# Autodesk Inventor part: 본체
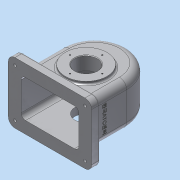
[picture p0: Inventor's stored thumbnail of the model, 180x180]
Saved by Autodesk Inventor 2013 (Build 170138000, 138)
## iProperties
Created: 2016-10
Part Number: 본체
Material: 알루미늄 6061
Document SubType Name: Modeling
Designer: dgall
Density: 2.71 g/cm^3
Mass: 1165.05 g
Surface Area: 1200.06 cm^2
Volume: 429.908 cm^3
Author: dgall
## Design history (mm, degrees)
sketch "스케치1" dims "d0" = 116
  geometry: L1 (-58, -80)-(58, -80); L2 (58, -80)-(58, 0); L3 (58, 0)-(-58, 0); L4 (-58, 0)-(-58, -80); 2 further points
  constraints: 8 end point, 2 parallel, 2 vertical, 1 coincident, 1 horizontal, 1 horizontal alignment, 1 perpendicular, 2 other
  dimensions: "d3" = 80 distance from line of L1 point (0, 0)
extrude "돌출1" new body sketch "스케치1" stored distance "d4" = 77; taper "d5" = 0 deg
sketch "스케치13"
  geometry: L1 (58, 0)-(58, -80) reference; L2 (58, -80)-(-58, -80) reference; L3 (-58, -80)-(-58, 0) reference; L4 (52, -80)-(52, 0); L5 (-52, 0)-(-52, -80); L6 (-52, -80)-(52, -80); A1 r 58 centre (0, 0) between (58, 0) and (-58, 0) reference; A2 r 52 centre (0, 0) between (52, 0) and (-52, 0); 1 further point
  constraints: 6 end point, 2 point on circle, 1 centre point, 1 perpendicular, 1 point on line, 2 other
  dimensions: "d126" = 6 distance between parallel lines of L1 L4
extrude "돌출8" cut sketch "스케치13" stored distance "d127" = 67; taper "d128" = 0 deg
fillet "모깎기1" dims "d25" = 13
sketch "스케치2"
  geometry: L1 (-58, -80)-(58, -80) reference; C1 r 37.5 at (0, -15); A1 r 58 centre (0, 0) between (58, 0) and (-58, 0) reference
  constraints: 1 centre point, 1 vertical alignment
  dimensions: "d7" = 65 distance from line of L1 C1.centre; "d8" = 75 diameter of C1
extrude "돌출2" join sketch "스케치2" distance "d9" = 5; taper "d10" = 0 deg
sketch "스케치3"
  geometry: L1 (-58, -80)-(58, -80) reference; C1 r 31 at (0, -15); A1 r 58 centre (0, 0) between (58, 0) and (-58, 0) reference
  constraints: 1 centre point, 1 vertical alignment
  dimensions: "d11" = 65 distance from line of L1 C1.centre; "d12" = 62 diameter of C1
extrude "돌출3" join sketch "스케치3" distance "d13" = 10; taper "d14" = 0 deg
node "작업 평면1"
sketch "스케치4"
  geometry: L1 (52, -65)-(-52, -65) reference; C1 r 28 at (0, 0); 1 further point
  constraints: 1 centre point, 1 vertical alignment
  dimensions: "d16" = 56 diameter of C1; "d129" = 65 distance from line of L1 C1.centre
extrude "돌출4" join sketch "스케치4" stored distance "d19" = 10; taper "d20" = 40 deg
sketch "스케치5"
  geometry: C1 r 31 at (0, 0) reference; C2 r 20 at (0, 0); 1 further point
  constraints: 1 centre point, 1 coincident
  dimensions: "d21" = 40 diameter of C2
extrude "돌출5" cut sketch "스케치5" stored distance "d23" = 10; taper "d24" = 0 deg
fillet "모깎기5" dims "d130" = 8
sketch "스케치7"
  geometry: L1 (98, -13)-(98, -64) reference; L2 (90, -72)-(0, -72) reference; L3 (-8, -64)-(-8, -13) reference; L4 (0, -5)-(90, -5) reference; L5 (0, 0)-(90, 0) reference; L6 (90, -77)-(0, -77) reference; L7 (103, -64)-(103, -13) reference; L8 (108, -93.5)-(-18, -93.5); L9 (-30, -81.5)-(-30, 4.5); L10 (-18, 16.5)-(108, 16.5); L11 (120, 4.5)-(120, -81.5); L12 (120, -93.5)-(-30, 16.5); L13 (-30, -93.5)-(120, 16.5); A1 r 8 centre (90, -13) between (98, -13) and (90, -5) reference; A2 r 8 centre (90, -64) between (90, -72) and (98, -64) reference; A3 r 8 centre (0, -64) between (-8, -64) and (0, -72) reference; A4 r 8 centre (0, -13) between (0, -5) and (-8, -13) reference; A5 r 13 centre (90, -13) between (103, -13) and (90, 0) reference; A6 r 13 centre (0, -64) between (-13, -64) and (0, -77) reference; A7 r 13 centre (90, -64) between (90, -77) and (103, -64) reference; A8 r 12 centre (-18, 4.5) between (-18, 16.5) and (-30, 4.5); A9 r 12 centre (108, 4.5) between (120, 4.5) and (108, 16.5); A10 r 12 centre (108, -81.5) between (108, -93.5) and (120, -81.5); A11 r 12 centre (-18, -81.5) between (-30, -81.5) and (-18, -93.5); 1 further point
  constraints: 12 end point, 8 point on circle, 8 point on line, 8 tangent, 4 centre point, 3 equal radius, 2 midpoint, 2 parallel, 1 horizontal, 1 perpendicular
  dimensions: "d31" = 150 distance of L12.end L13.end; "d33" = 110 distance of L13.start L12.end; "d34" = 12 radius of A8
extrude "돌출6" join sketch "스케치7" distance "d35" = 15; taper "d36" = 0 deg
node "작업 평면3"
sketch "스케치8"
  geometry: C1 r 6 at (63, 55); 1 further point
  constraints: 1 centre point, 1 coincident
  dimensions: "d76" = 12 diameter of C1
extrude "돌출7" join sketch "스케치8" stored distance "d78" = 15; taper "d79" = 10 deg
sketch "스케치9"
  geometry: L1 (108, 81.5)-(-18, 81.5); L2 (-18, 81.5)-(-18, -4.5); L3 (-18, -4.5)-(108, -4.5); L4 (108, -4.5)-(108, 81.5); A1 r 12 centre (-18, -4.5) between (-30, -4.5) and (-18, -16.5) reference; A2 r 12 centre (108, 81.5) between (120, 81.5) and (108, 93.5) reference; A3 r 12 centre (-18, 81.5) between (-18, 93.5) and (-30, 81.5) reference; 1 further point
  constraints: 8 end point, 2 parallel, 1 horizontal, 1 perpendicular
hole "구멍5" sketch "스케치9" at (108, -4.5), (-18, -4.5), (108, 81.5), (-18, 81.5) diameter "d80" = 5; stored, may be unused: countersink angle "d84" = 90 deg, drill point angle "d86" = 118 deg; dims "d81" = 6, "d82" = 12, "d83" = 5, "d85" = 8
hole "구멍6" diameter "d89" = 4.459; stored, may be unused: countersink angle "d93" = 90 deg, drill point angle "d95" = 118 deg; dims "d87" = 10, "d88" = 10, "d90" = 6, "d91" = 12, "d92" = 5, "d94" = 8
sketch "스케치10"
  geometry: C1 r 20 at (0, 0) reference; 2 further points
  constraints: 1 vertical alignment
  dimensions: "d96" = 29 distance of C1.centre point (0, 29)
hole "구멍7" sketch "스케치10" at (0, 29) diameter "d97" = 2.459; stored, may be unused: countersink angle "d101" = 90 deg, drill point angle "d103" = 118 deg; dims "d98" = 6, "d99" = 12, "d100" = 5, "d102" = 8
sketch "스케치11"
  geometry: C1 r 20 at (0, 0) reference; 2 further points
  constraints: 1 vertical alignment
  dimensions: "d104" = 26 distance of C1.centre point (0, 26)
hole "구멍8" sketch "스케치11" at (0, 26) diameter "d105" = 2.459; stored, may be unused: countersink angle "d109" = 90 deg, drill point angle "d111" = 118 deg; dims "d106" = 6, "d107" = 12, "d108" = 5, "d110" = 8
sketch "스케치12"
  geometry: L1 (86, 0)-(0, 0) reference; L2 (4.5, 80)-(4.5, 15) reference; 2 further points
  constraints: 1 other
  dimensions: "d118" = 38.5 distance from line of point (43, 40) L2; "d119" = 40 distance from line of point (43, 40) L1
feature "엠보싱1" sketch "스케치12" dims "d0" = 116, "d3" = 80, "d11" = 65, "d12" = 62, "d120" = 0.5, "d121" = 0
fillet "모깎기4" dims "d122" = 3
chamfer "모따기1" distance "d123" = 1; stored, may be unused: second distance "d124" = 2, angle "d125" = 45 deg
node "솔리드1"
pattern_circular "원형 패턴1" dims angle "d113" = 360 deg
pattern_circular "원형 패턴2" dims angle "d116" = 360 deg
node "절단 모서리 투영1"
other parameters: "d15" = -24, "d75" = -144
